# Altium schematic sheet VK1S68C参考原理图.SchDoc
size A3
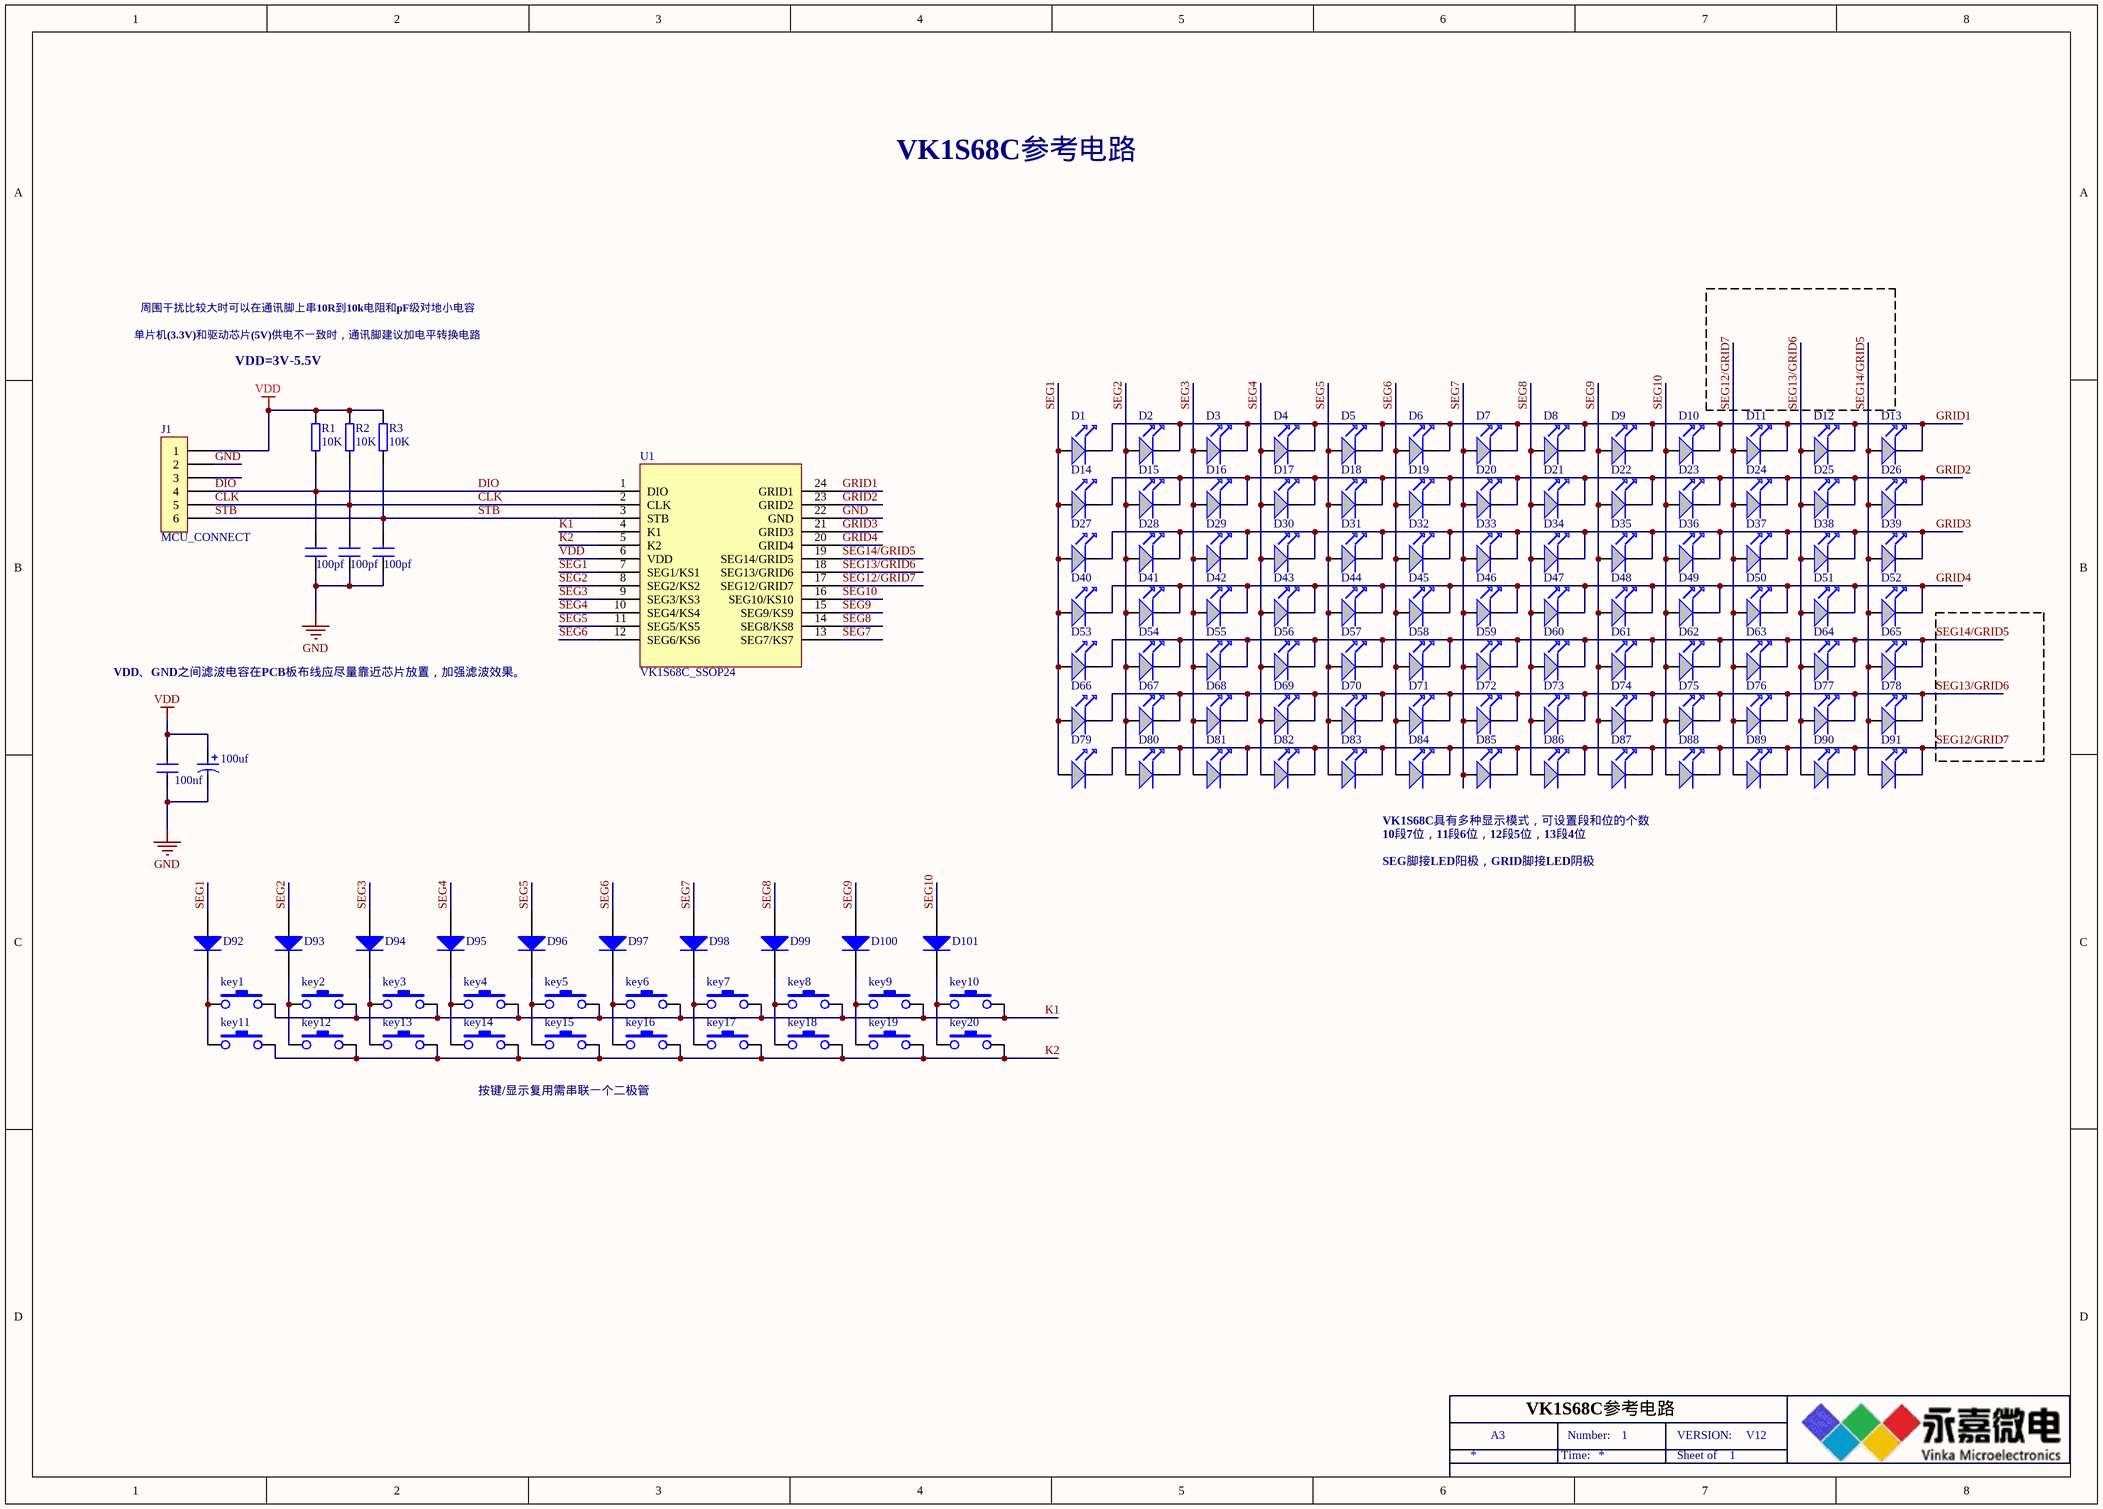
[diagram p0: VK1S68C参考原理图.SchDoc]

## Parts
100nf  CAP  (value not drawn)
100pf  CAP  (value not drawn)
100pf1  100pf
100pf3  100pf
100uf  CAP2  (value not drawn)
D1  (no value)  [1206-LED]
D2  (no value)  [1206-LED]
D3  (no value)  [1206-LED]
D4  (no value)  [1206-LED]
D5  (no value)  [1206-LED]
D6  (no value)  [1206-LED]
D7  (no value)  [1206-LED]
D8  (no value)  [1206-LED]
D9  (no value)  [1206-LED]
D10  (no value)  [1206-LED]
D11  (no value)  [1206-LED]
D12  (no value)  [1206-LED]
D13  (no value)  [1206-LED]
D14  (no value)  [1206-LED]
D15  (no value)  [1206-LED]
D16  (no value)  [1206-LED]
D17  (no value)  [1206-LED]
D18  (no value)  [1206-LED]
D19  (no value)  [1206-LED]
D20  (no value)  [1206-LED]
D21  (no value)  [1206-LED]
D22  (no value)  [1206-LED]
D23  (no value)  [1206-LED]
D24  (no value)  [1206-LED]
D25  (no value)  [1206-LED]
D26  (no value)  [1206-LED]
D27  (no value)  [1206-LED]
D28  (no value)  [1206-LED]
D29  (no value)  [1206-LED]
D30  (no value)  [1206-LED]
D31  (no value)  [1206-LED]
D32  (no value)  [1206-LED]
D33  (no value)  [1206-LED]
D34  (no value)  [1206-LED]
D35  (no value)  [1206-LED]
D36  (no value)  [1206-LED]
D37  (no value)  [1206-LED]
D38  (no value)  [1206-LED]
D39  (no value)  [1206-LED]
D40  (no value)  [1206-LED]
D41  (no value)  [1206-LED]
D42  (no value)  [1206-LED]
D43  (no value)  [1206-LED]
D44  (no value)  [1206-LED]
D45  (no value)  [1206-LED]
D46  (no value)  [1206-LED]
D47  (no value)  [1206-LED]
D48  (no value)  [1206-LED]
D49  (no value)  [1206-LED]
D50  (no value)  [1206-LED]
D51  (no value)  [1206-LED]
D52  (no value)  [1206-LED]
D53  (no value)  [1206-LED]
D54  (no value)  [1206-LED]
D55  (no value)  [1206-LED]
D56  (no value)  [1206-LED]
D57  (no value)  [1206-LED]
D58  (no value)  [1206-LED]
D59  (no value)  [1206-LED]
D60  (no value)  [1206-LED]
D61  (no value)  [1206-LED]
D62  (no value)  [1206-LED]
D63  (no value)  [1206-LED]
D64  (no value)  [1206-LED]
D65  (no value)  [1206-LED]
D66  (no value)  [1206-LED]
D67  (no value)  [1206-LED]
D68  (no value)  [1206-LED]
D69  (no value)  [1206-LED]
D70  (no value)  [1206-LED]
D71  (no value)  [1206-LED]
D72  (no value)  [1206-LED]
D73  (no value)  [1206-LED]
D74  (no value)  [1206-LED]
D75  (no value)  [1206-LED]
D76  (no value)  [1206-LED]
D77  (no value)  [1206-LED]
D78  (no value)  [1206-LED]
D79  (no value)  [1206-LED]
D80  (no value)  [1206-LED]
D81  (no value)  [1206-LED]
D82  (no value)  [1206-LED]
D83  (no value)  [1206-LED]
D84  (no value)  [1206-LED]
D85  (no value)  [1206-LED]
D86  (no value)  [1206-LED]
D87  (no value)  [1206-LED]
D88  (no value)  [1206-LED]
D89  (no value)  [1206-LED]
D90  (no value)  [1206-LED]
D91  (no value)  [1206-LED]
D92  Diode 1N4003  [DO-41]  (value not drawn)
D93  Diode 1N4003  [DO-41]  (value not drawn)
D94  Diode 1N4003  [DO-41]  (value not drawn)
D95  Diode 1N4003  [DO-41]  (value not drawn)
D96  Diode 1N4003  [DO-41]  (value not drawn)
D97  Diode 1N4003  [DO-41]  (value not drawn)
D98  Diode 1N4003  [DO-41]  (value not drawn)
D99  Diode 1N4003  [DO-41]  (value not drawn)
D100  Diode 1N4003  [DO-41]  (value not drawn)
D101  Diode 1N4003  [DO-41]  (value not drawn)
J1  MCU_CONNECT
key1  KEY  [AN12]  (value not drawn)
key2  KEY  [AN12]  (value not drawn)
key3  KEY  [AN12]  (value not drawn)
key4  KEY  [AN12]  (value not drawn)
key5  KEY  [AN12]  (value not drawn)
key6  KEY  [AN12]  (value not drawn)
key7  KEY  [AN12]  (value not drawn)
key8  KEY  [AN12]  (value not drawn)
key9  KEY  [AN12]  (value not drawn)
key10  KEY  [AN12]  (value not drawn)
key11  KEY  [AN12]  (value not drawn)
key12  KEY  [AN12]  (value not drawn)
key13  KEY  [AN12]  (value not drawn)
key14  KEY  [AN12]  (value not drawn)
key15  KEY  [AN12]  (value not drawn)
key16  KEY  [AN12]  (value not drawn)
key17  KEY  [AN12]  (value not drawn)
key18  KEY  [AN12]  (value not drawn)
key19  KEY  [AN12]  (value not drawn)
key20  KEY  [AN12]  (value not drawn)
R1  10K  [0603-R]
R2  10K  [0603-R]
R3  10K  [0603-R]
U1  VK1S68C_SSOP24

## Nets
GND: 100nf.2 100pf.2 100pf1.2 100pf3.2 100uf.2 J1.2 U1.22(GND)
VDD: 100nf.1 100uf.1 J1.1 R1.1 R2.1 R3.1 U1.6(VDD)
CLK: 100pf3.1 J1.5 R2.2 U1.2(CLK)
DIO: 100pf1.1 J1.4 R1.2 U1.1(DIO)
GRID1: D1.2 D2.2 D3.2 D4.2 D5.2 D6.2 D7.2 D8.2 D9.2 D10.2 D11.2 D12.2 D13.2 U1.24(GRID1)
GRID2: D14.2 D15.2 D16.2 D17.2 D18.2 D19.2 D20.2 D21.2 D22.2 D23.2 D24.2 D25.2 D26.2 U1.23(GRID2)
GRID3: D27.2 D28.2 D29.2 D30.2 D31.2 D32.2 D33.2 D34.2 D35.2 D36.2 D37.2 D38.2 D39.2 U1.21(GRID3)
GRID4: D40.2 D41.2 D42.2 D43.2 D44.2 D45.2 D46.2 D47.2 D48.2 D49.2 D50.2 D51.2 D52.2 U1.20(GRID4)
K1: key1.2 key2.2 key3.2 key4.2 key5.2 key6.2 key7.2 key8.2 key9.2 key10.2 U1.4(K1)
K2: key11.2 key12.2 key13.2 key14.2 key15.2 key16.2 key17.2 key18.2 key19.2 key20.2 U1.5(K2)
SEG1: D1.1 D14.1 D27.1 D40.1 D53.1 D66.1 D79.1 D92.1(A) U1.7(SEG1/KS1)
SEG2: D2.1 D15.1 D28.1 D41.1 D54.1 D67.1 D80.1 D93.1(A) U1.8(SEG2/KS2)
SEG3: D3.1 D16.1 D29.1 D42.1 D55.1 D68.1 D81.1 D94.1(A) U1.9(SEG3/KS3)
SEG4: D4.1 D17.1 D30.1 D43.1 D56.1 D69.1 D82.1 D95.1(A) U1.10(SEG4/KS4)
SEG5: D5.1 D18.1 D31.1 D44.1 D57.1 D70.1 D83.1 D96.1(A) U1.11(SEG5/KS5)
SEG6: D6.1 D19.1 D32.1 D45.1 D58.1 D71.1 D84.1 D97.1(A) U1.12(SEG6/KS6)
SEG7: D7.1 D20.1 D33.1 D46.1 D59.1 D72.1 D85.1 D98.1(A) U1.13(SEG7/KS7)
SEG8: D8.1 D21.1 D34.1 D47.1 D60.1 D73.1 D86.1 D99.1(A) U1.14(SEG8/KS8)
SEG9: D9.1 D22.1 D35.1 D48.1 D61.1 D74.1 D87.1 D100.1(A) U1.15(SEG9/KS9)
SEG10: D10.1 D23.1 D36.1 D49.1 D62.1 D75.1 D88.1 D101.1(A) U1.16(SEG10/KS10)
SEG12/GRID7: D11.1 D24.1 D37.1 D50.1 D63.1 D76.1 D79.2 D80.2 D81.2 D82.2 D83.2 D84.2 D85.2 D86.2 D87.2 D88.2 D89.1 D89.2 D90.2 D91.2 U1.17(SEG12/GRID7)
SEG13/GRID6: D12.1 D25.1 D38.1 D51.1 D64.1 D66.2 D67.2 D68.2 D69.2 D70.2 D71.2 D72.2 D73.2 D74.2 D75.2 D76.2 D77.1 D77.2 D78.2 D90.1 U1.18(SEG13/GRID6)
SEG14/GRID5: D13.1 D26.1 D39.1 D52.1 D53.2 D54.2 D55.2 D56.2 D57.2 D58.2 D59.2 D60.2 D61.2 D62.2 D63.2 D64.2 D65.1 D65.2 D78.1 D91.1 U1.19(SEG14/GRID5)
STB: 100pf.1 J1.6 R3.2 U1.3(STB)
NetD92_2: D92.2(K) key1.1 key11.1
NetD93_2: D93.2(K) key2.1 key12.1
NetD94_2: D94.2(K) key3.1 key13.1
NetD95_2: D95.2(K) key4.1 key14.1
NetD96_2: D96.2(K) key5.1 key15.1
NetD97_2: D97.2(K) key6.1 key16.1
NetD98_2: D98.2(K) key7.1 key17.1
NetD99_2: D99.2(K) key8.1 key18.1
NetD100_2: D100.2(K) key9.1 key19.1
NetD101_2: D101.2(K) key10.1 key20.1

Not connected (* = marked no-connect by the designer): J1 3

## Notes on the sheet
- VK1S68C参考电路
- 周围干扰比较大时可以在通讯脚上串10R到10k电阻和pF级对地小电容
- 单片机(3.3V)和驱动芯片(5V)供电不一致时，通讯脚建议加电平转换电路
- VDD=3V-5.5V
- VDD、GND之间滤波电容在PCB板布线应尽量靠近芯片放置，加强滤波效果。
- 10段7位，11段6位，12段5位，13段4位
- VK1S68C具有多种显示模式，可设置段和位的个数
- SEG脚接LED阳极，GRID脚接LED阴极
- 按键/显示复用需串联一个二极管
- A3
- Time:
- Number:
- 1
- Sheet of
- VERSION:
- V12

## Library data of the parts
100nf 100pf 100pf1 100pf3 = CAP: Capacitor
100uf = CAP2: Bi-Polar Capacitor
D1-D91 = LED: Text Field1: 30; Text Field2: 20
D92-D101 = Diode 1N4003: 1 Amp General Purpose Rectifier
J1 = CON6: Connector
R1-R3 = RES: Resistor
U1 = VK1S68C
